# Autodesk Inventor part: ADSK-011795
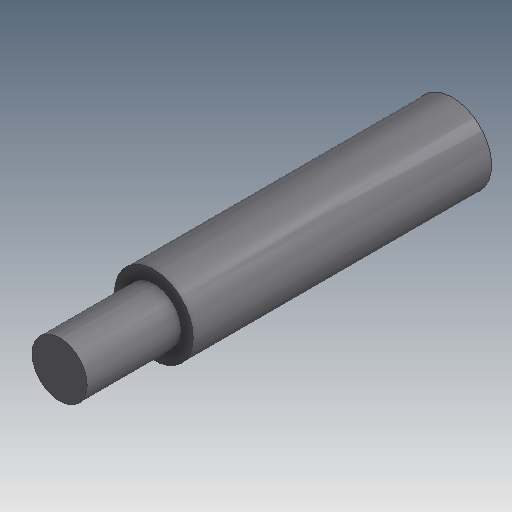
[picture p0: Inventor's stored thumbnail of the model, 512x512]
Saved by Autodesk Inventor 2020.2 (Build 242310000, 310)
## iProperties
Created: 1999-11
Part Number: ADSK-011795
Material: Acier doux
Document SubType Name: Modeling
Designer: kcovelli
Density: 7.86 g/cm^3
Appearance: Metal-Steel(Polish)
Mass: 108.373 g
Surface Area: 40.6949 cm^2
Volume: 13.7879 cm^3
Control State: 0
Master: False
Checked Out: False
Shininess: 0.0
Length Units: 11272
Angle Units: 11279
Time Units: 11290
Mass Units: 11286
Length Display Precision: 3
Angle Display Precision: 2
Compacted: True
Dimensions: 0,6x3,1x0,6 in
Mass: 0,239 lb
VLT_Material: Acier doux
Density: 0.0
Volumn: 0.0
Area: 0.0
PropertySet Name: Model Information
Author: kcovelli
Revision Number: -
Title: ADSK-011795
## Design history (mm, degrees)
node "Extrusion1" dims "d0" = 50.8, "d1" = 0
node "Extrusion2" dims "d2" = 9.525, "d3" = 0
node "Extrusion3" dims "d5" = 19.05, "d6" = 0
node "Solide1"
node "Corps solides"
node "Corps surfaciques"
sketch "Sketch1"
  geometry: C1 r 7.938 at (-1.105, 0)
  constraints: 1 centre point
  dimensions: "d7" = 15.875 diameter of C1
sketch "Sketch2"
  geometry: C1 r 7.937 at (0, 0) reference
sketch "Sketch3"
  geometry: C1 r 7.937 at (0, 0) reference; C2 r 5.556 at (0, 0)
  constraints: 1 centre point, 1 coincident
  dimensions: "d4" = 11.1125 diameter of C2
